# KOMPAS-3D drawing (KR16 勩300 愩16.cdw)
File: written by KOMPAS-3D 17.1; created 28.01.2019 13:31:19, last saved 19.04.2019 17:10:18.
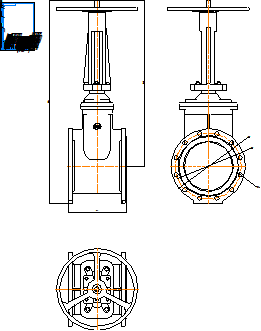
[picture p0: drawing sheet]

Sheet 1: A4, portrait

Title block, sheet 1: name: KR16 Ду300 Ру16; material: Внимание! Данный продукт является объектом авторского права ООО «Торговый Дом АДЛ». / Запрещается изменение, копирование, распространение / (в том числе путем копирования на другие сайты и ресурсы в Интернете) / или любое иное использование информации и объектов без предварительного / согласия правообладателя (ООО «Торговый Дом АДЛ»).; sheets: 1; organisation: ООО "Торговый дом АДЛ"; sheet format: A4; stored path: \\adlc.lan\data\АДЛ_ПКД\3D-модели\ADL production\Клиновые задвижки серии KR ГРАНАР\Клиновые задвижки KR16\Со штурвалом\KOMPAS 2D\KR16 Ду300.cdw

Views: Вид 1, Проекционный вид 2
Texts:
  user
Dimensions and other numbers on the sheet: 356; 1020,1; 1251,6; 460; 26; 12 отв.; 410; 1:1; 1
